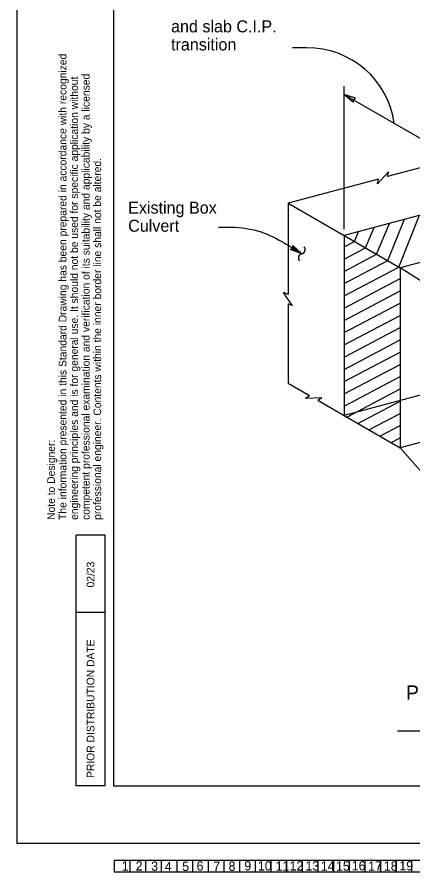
# Model space of a CAD drawing. Extents: x 0 to 2.83, y -0.03 to 1.83.
# Drawn here: x 0 to 0.428, y -0.031 to 0.894 of the extents above; entities that cross this region are included whole.
import ezdxf

# ---------------------------------------------------------------- set-up
doc = ezdxf.new("R2010")
doc.units = 0
for name, color, linetype in [('1', 7, 'Continuous'), ('10', 7, 'Continuous'), ('11', 7, 'Continuous'), ('12', 7, 'Continuous'), ('13', 7, 'Continuous'), ('14', 7, 'Continuous'), ('15', 7, 'Continuous'), ('16', 7, 'Continuous'), ('17', 7, 'Continuous'), ('18', 7, 'Continuous'), ('19', 7, 'Continuous'), ('2', 7, 'Continuous'), ('3', 7, 'Continuous'), ('4', 7, 'Continuous'), ('5', 7, 'Continuous'), ('50', 7, 'Continuous'), ('54', 7, 'Continuous'), ('55', 7, 'Continuous'), ('57', 7, 'Continuous'), ('6', 7, 'Continuous'), ('62', 7, 'Continuous'), ('63', 7, 'Continuous'), ('7', 7, 'Continuous'), ('8', 7, 'Continuous'), ('9', 7, 'Continuous'), ('Default', 7, 'Continuous')]:
    doc.layers.add(name, color=color, linetype=linetype)

msp = doc.modelspace()

# ---------------------------------------------------------------- linework, layer by layer
at = {"layer": '50'}
for p, q in [((0.5489, 0.70987), (0.35365, 0.65755)), ((0.60944, 0.67492), (0.41419, 0.6226)), ((0.35365, 0.65755), (0.41419, 0.6226)), ((0.35365, 0.65755), (0.35365, 0.46286)), ((0.41419, 0.6226), (0.41419, 0.42791)), ((0.35365, 0.46286), (0.41419, 0.42791))]:
    msp.add_line(p, q, dxfattribs=at)
at = {"layer": '54'}
msp.add_lwpolyline([(0.35365, 0.81012), (0.36391, 0.80182), (0.36373, 0.80462), (0.36607, 0.80608)], close=True, dxfattribs=at)
at = {"layer": '55'}
for p, q in [((0.313, 0.86039), (0.29777, 0.86039)), ((0.35365, 0.66459), (0.35365, 0.81904)), ((0.38967, 0.71361), (0.40175, 0.72635)), ((0.4007, 0.72134), (0.40175, 0.72635)), ((0.38967, 0.71361), (0.39073, 0.71867)), ((0.29311, 0.59375), (0.28824, 0.59607)), ((0.29777, 0.58133), (0.28824, 0.59607)), ((0.29777, 0.58133), (0.29311, 0.58355)), ((0.31194, 0.48159), (0.31625, 0.48445)), ((0.31194, 0.48159), (0.32949, 0.4822)), ((0.32515, 0.47931), (0.32949, 0.4822))]:
    msp.add_line(p, q, dxfattribs=at)
for points in [[(0.30786, 0.63776), (0.29561, 0.64254), (0.29758, 0.64352), (0.30529, 0.63935), (0.29808, 0.64439), (0.29809, 0.64659), (0.30784, 0.63778)], [(0.30346, 0.63982), (0.29791, 0.64292), (0.29692, 0.6425), (0.30662, 0.63852), (0.29871, 0.64542), (0.29878, 0.64431), (0.30385, 0.64094)]]:
    msp.add_lwpolyline(points, dxfattribs=at)
for centre, radius, start, end in [((0.31449, 0.76621), 0.09419, 7.70857, 90.90705), ((0.30678, 0.64236), 0.0047, 283.04492, 39.45098), ((0.3089, 0.6332), 0.0047, 103.04492, 219.45098)]:
    msp.add_arc(centre, radius, start, end, dxfattribs=at)
msp.add_spline([(0.21791, 0.66663), (0.2313, 0.66663), (0.26383, 0.66138), (0.28871, 0.64958), (0.30784, 0.63778)], degree=3, dxfattribs=at)
at = {"layer": '62'}
for p, q in [((0.10494, -0.01804), (0.10494, -0.03074)), ((0.10494, -0.01804), (1.17174, -0.01804)), ((0.10496, -0.0181), (0.10496, -0.0308)), ((0.10496, -0.0181), (1.17175, -0.0181)), ((0.12188, -0.01804), (0.12188, -0.03074)), ((0.12189, -0.0181), (0.12189, -0.0308)), ((0.13881, -0.01804), (0.13881, -0.03074)), ((0.13882, -0.0181), (0.13882, -0.0308)), ((0.15574, -0.01804), (0.15574, -0.03074)), ((0.15576, -0.0181), (0.15576, -0.0308)), ((0.17267, -0.01804), (0.17267, -0.03074)), ((0.17269, -0.0181), (0.17269, -0.0308)), ((0.18961, -0.01804), (0.18961, -0.03074)), ((0.18962, -0.0181), (0.18962, -0.0308)), ((0.20654, -0.01804), (0.20654, -0.03074)), ((0.20656, -0.0181), (0.20656, -0.0308)), ((0.22348, -0.01804), (0.22348, -0.03074)), ((0.22349, -0.0181), (0.22349, -0.0308)), ((0.24041, -0.01804), (0.24041, -0.03074)), ((0.24042, -0.0181), (0.24042, -0.0308)), ((0.25734, -0.01804), (0.25734, -0.03074)), ((0.25736, -0.0181), (0.25736, -0.0308)), ((0.27427, -0.01804), (0.27427, -0.03074)), ((0.27429, -0.0181), (0.27429, -0.0308)), ((0.29121, -0.01804), (0.29121, -0.03074)), ((0.29122, -0.0181), (0.29122, -0.0308)), ((0.30814, -0.01804), (0.30814, -0.03074)), ((0.30816, -0.0181), (0.30816, -0.0308)), ((0.32508, -0.01804), (0.32508, -0.03074)), ((0.32509, -0.0181), (0.32509, -0.0308)), ((0.34201, -0.01804), (0.34201, -0.03074)), ((0.34202, -0.0181), (0.34202, -0.0308)), ((0.35894, -0.01804), (0.35894, -0.03074)), ((0.35896, -0.0181), (0.35896, -0.0308)), ((0.37588, -0.01804), (0.37588, -0.03074)), ((0.37589, -0.0181), (0.37589, -0.0308)), ((0.39281, -0.01804), (0.39281, -0.03074)), ((0.39282, -0.0181), (0.39282, -0.0308)), ((0.40974, -0.01804), (0.40974, -0.03074)), ((0.40976, -0.0181), (0.40976, -0.0308)), ((0.42668, -0.01804), (0.42668, -0.03074)), ((0.42669, -0.0181), (0.42669, -0.0308)), ((0.10494, -0.03074), (1.17174, -0.03074)), ((0.10496, -0.0308), (1.17175, -0.0308))]:
    msp.add_line(p, q, dxfattribs=at)
at = {"layer": '63'}
for p, q in [((0, 0), (0, 1.83333)), ((0.06381, 0.06244), (0.06381, 0.33328)), ((0.09506, 0.33328), (0.06381, 0.33328)), ((0.09506, 0.06244), (0.09506, 0.33328)), ((0.09506, 0.24994), (0.06381, 0.24994)), ((0.09506, 0.06244), (0.06381, 0.06244)), ((2.83333, 0), (0, 0))]:
    msp.add_line(p, q, dxfattribs=at)
msp.add_lwpolyline([(2.72918, 1.77077), (0.10418, 1.77077), (0.10418, 0.06244), (2.72918, 0.06244)], close=True, dxfattribs=at)
at = {"layer": 'Default'}
for p, q in [((0.35365, 0.81012), (0.462, 0.74756)), ((0.48836, 0.74483), (0.4007, 0.72134)), ((0.39073, 0.71867), (0.29311, 0.69251)), ((0.29311, 0.69251), (0.29311, 0.59375)), ((0.29311, 0.69251), (0.35365, 0.65755)), ((0.40076, 0.63035), (0.41893, 0.67505)), ((0.41275, 0.62343), (0.43528, 0.67943)), ((0.37678, 0.6442), (0.38622, 0.66628)), ((0.38877, 0.63728), (0.40258, 0.67066)), ((0.36478, 0.65112), (0.36933, 0.66176)), ((0.35365, 0.64525), (0.36478, 0.65112)), ((0.35365, 0.632), (0.37678, 0.6442)), ((0.35365, 0.61875), (0.38877, 0.63728)), ((0.35365, 0.6055), (0.40076, 0.63035)), ((0.35365, 0.59225), (0.41275, 0.62343)), ((0.462, 0.592), (0.41419, 0.6226)), ((0.35365, 0.579), (0.41419, 0.61094)), ((0.35365, 0.56575), (0.41419, 0.59769)), ((0.29311, 0.58355), (0.29311, 0.49781)), ((0.35365, 0.5525), (0.41419, 0.58444)), ((0.35365, 0.53925), (0.41419, 0.57119)), ((0.35365, 0.526), (0.41419, 0.55794)), ((0.35365, 0.51275), (0.41419, 0.54469)), ((0.35365, 0.49951), (0.41419, 0.53144)), ((0.35365, 0.48626), (0.41419, 0.51819)), ((0.5489, 0.51518), (0.35365, 0.46286)), ((0.35365, 0.47301), (0.41419, 0.50494)), ((0.29311, 0.49781), (0.31625, 0.48445)), ((0.35645, 0.46124), (0.41419, 0.49169)), ((0.32515, 0.47931), (0.35365, 0.46286)), ((0.36844, 0.45431), (0.41419, 0.47844)), ((0.60944, 0.48022), (0.41419, 0.42791)), ((0.38044, 0.44739), (0.41419, 0.46519)), ((0.39243, 0.44047), (0.41419, 0.45195)), ((0.40442, 0.43354), (0.41419, 0.4387)), ((0.462, 0.37372), (0.41419, 0.42791)), ((0.41123, 0.12167), (0.82679, 0.12167))]:
    msp.add_line(p, q, dxfattribs=at)

# ---------------------------------------------------------------- texts
at = {"layer": '1'}
for p in [(0.11316, -0.02944), (0.11317, -0.02949)]:
    msp.add_text('1', height=0.01, rotation=360, dxfattribs=at).set_placement(p)
at = {"layer": '10'}
for p in [(0.26046, -0.02928), (0.26047, -0.02934)]:
    msp.add_text('10', height=0.01, rotation=360, dxfattribs=at).set_placement(p)
at = {"layer": '11'}
for p in [(0.2796, -0.02937), (0.27961, -0.02942)]:
    msp.add_text('11', height=0.01, rotation=360, dxfattribs=at).set_placement(p)
at = {"layer": '12'}
for p in [(0.29469, -0.02925), (0.29471, -0.0293)]:
    msp.add_text('12', height=0.01, rotation=360, dxfattribs=at).set_placement(p)
at = {"layer": '13'}
for p in [(0.31181, -0.02928), (0.31182, -0.02933)]:
    msp.add_text('13', height=0.01, rotation=360, dxfattribs=at).set_placement(p)
at = {"layer": '14'}
for p in [(0.32844, -0.02939), (0.32846, -0.02944)]:
    msp.add_text('14', height=0.01, rotation=360, dxfattribs=at).set_placement(p)
at = {"layer": '15'}
for p in [(0.34488, -0.02946), (0.34489, -0.02951)]:
    msp.add_text('15', height=0.01, rotation=360, dxfattribs=at).set_placement(p)
at = {"layer": '16'}
for p in [(0.3619, -0.02918), (0.36191, -0.02923)]:
    msp.add_text('16', height=0.01, rotation=360, dxfattribs=at).set_placement(p)
at = {"layer": '17'}
for p in [(0.3797, -0.02946), (0.37971, -0.02951)]:
    msp.add_text('17', height=0.01, rotation=360, dxfattribs=at).set_placement(p)
at = {"layer": '18'}
for p in [(0.39663, -0.02938), (0.39664, -0.02943)]:
    msp.add_text('18', height=0.01, rotation=360, dxfattribs=at).set_placement(p)
at = {"layer": '19'}
for p in [(0.4134, -0.02918), (0.41342, -0.02923)]:
    msp.add_text('19', height=0.01, rotation=360, dxfattribs=at).set_placement(p)
at = {"layer": '2'}
for p in [(0.12828, -0.02928), (0.12829, -0.02934)]:
    msp.add_text('2', height=0.01, rotation=360, dxfattribs=at).set_placement(p)
at = {"layer": '3'}
for p in [(0.145, -0.02955), (0.14501, -0.02961)]:
    msp.add_text('3', height=0.01, rotation=360, dxfattribs=at).set_placement(p)
at = {"layer": '4'}
for p in [(0.15973, -0.02984), (0.15975, -0.0299)]:
    msp.add_text('4', height=0.01, rotation=360, dxfattribs=at).set_placement(p)
at = {"layer": '5'}
for p in [(0.17858, -0.02977), (0.17859, -0.02982)]:
    msp.add_text('5', height=0.01, rotation=360, dxfattribs=at).set_placement(p)
at = {"layer": '57'}
for s, height, p in [('and slab C.I.P.', 0.0130208, (0.16649, 0.87727)), ('transition', 0.013021, (0.16649, 0.85774)), ('Existing Box', 0.0130208, (0.12011, 0.68115)), ('Culvert', 0.013021, (0.12011, 0.66162))]:
    msp.add_text(s, height=height, dxfattribs=at).set_placement(p)
at = {"layer": '6'}
for p in [(0.19409, -0.02938), (0.19411, -0.02943)]:
    msp.add_text('6', height=0.01, rotation=360, dxfattribs=at).set_placement(p)
at = {"layer": '62'}
for s, height, p in [('The information presented in this Standard Drawing has been prepared in accordance with recognized', 0.0083333, (0.05339, 0.34994)), ('engineering principles and is for general use. It should not be used for specific application without', 0.00833333, (0.06589, 0.34994)), ('competent professional examination and verification of its suitability and applicability by a licensed', 0.00833333, (0.07839, 0.34994)), ('professional engineer. Contents within the inner border line shall not be altered.', 0.0083333, (0.09089, 0.34994)), ('Note to Designer:', 0.0083333, (0.04089, 0.34994))]:
    msp.add_text(s, height=height, rotation=90, dxfattribs=at).set_placement(p)
at = {"layer": '63'}
for s, height, p in [('02/23', 0.008333, (0.0836, 0.27689)), ('PRIOR DISTRIBUTION DATE', 0.0083333, (0.0836, 0.07078))]:
    msp.add_text(s, height=height, rotation=90, dxfattribs=at).set_placement(p)
at = {"layer": '7'}
for p in [(0.21211, -0.02964), (0.21212, -0.02969)]:
    msp.add_text('7', height=0.01, rotation=360, dxfattribs=at).set_placement(p)
at = {"layer": '8'}
for p in [(0.22865, -0.02958), (0.22866, -0.02963)]:
    msp.add_text('8', height=0.01, rotation=360, dxfattribs=at).set_placement(p)
at = {"layer": '9'}
for p in [(0.24573, -0.02921), (0.24574, -0.02926)]:
    msp.add_text('9', height=0.01, rotation=360, dxfattribs=at).set_placement(p)
at = {"layer": 'Default'}
msp.add_text('PICTORIAL VIEW OF EXTERIOR', height=0.015625, dxfattribs=at).set_placement((0.42058, 0.15533))

doc.saveas('drawing.dxf')
